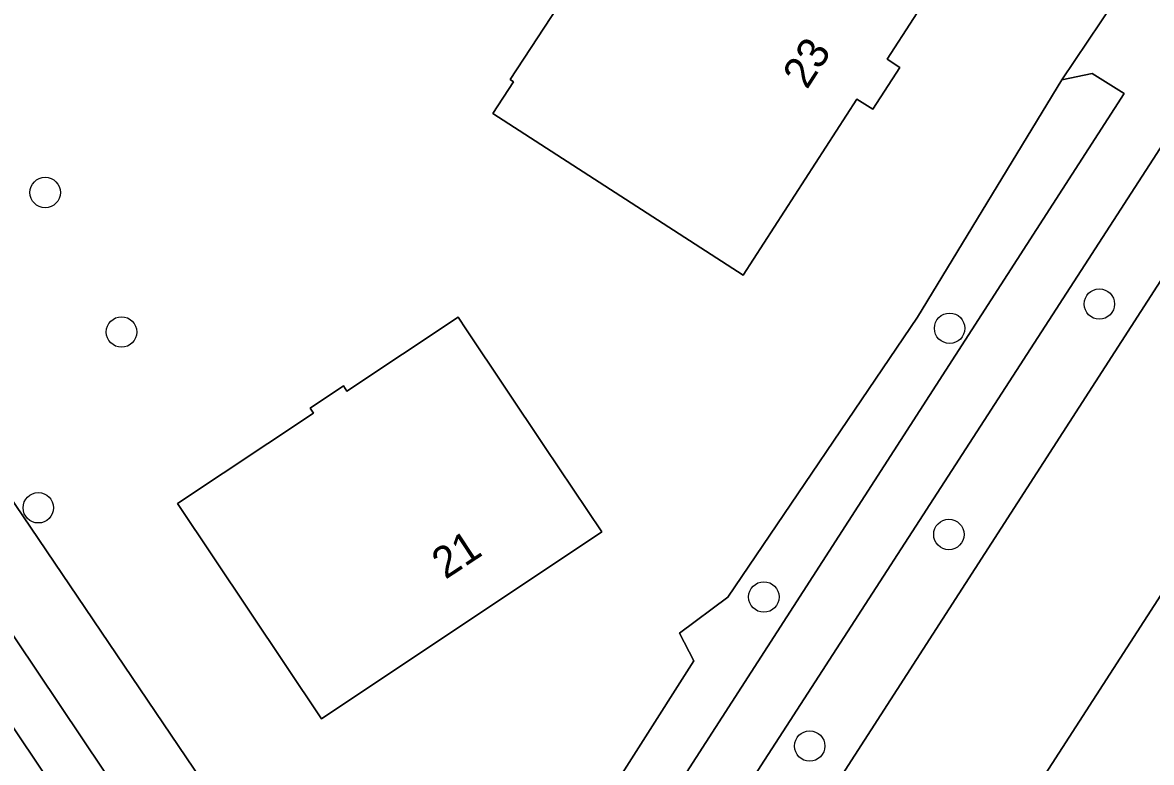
# Model space of a CAD drawing. Extents: x 158793 to 159888, y 384317 to 385256.
# Drawn here: x 158908.93 to 158945.21, y 384709.07 to 384732.84 of the extents above; entities that cross this region are included whole.
import ezdxf

# ---------------------------------------------------------------- set-up
doc = ezdxf.new("R2010")
doc.units = 0
for name, color, linetype in [('IMGEO_Berm_groen', 7, 'Continuous'), ('IMGEO_Boom', 7, 'Continuous'), ('IMGEO_Erf', 7, 'Continuous'), ('IMGEO_Groenvoorziening', 7, 'Continuous'), ('IMGEO_Pand', 7, 'Continuous'), ('IMGEO_Pand_nummerreeks', 7, 'Continuous'), ('IMGEO_Rijbaan_lokaal_open', 7, 'Continuous'), ('IMGEO_Voetpad_gesloten', 7, 'Continuous'), ('IMGEO_Voetpad_open', 7, 'Continuous')]:
    doc.layers.add(name, color=color, linetype=linetype)

msp = doc.modelspace()

# ---------------------------------------------------------------- linework, layer by layer
at = {"layer": 'IMGEO_Berm_groen'}
msp.add_lwpolyline([(158947.905, 384728.262), (158945.951, 384729.508), (158927.819, 384701.473), (158929.826, 384700.232)], close=True, dxfattribs=at)
msp.add_lwpolyline([(158951.852, 384724.265), (158938.197, 384703.116), (158942.084, 384700.551), (158942.526, 384699.967), (158952.229, 384685.559)], dxfattribs=at)
at = {"layer": 'IMGEO_Boom'}
for centre in [(158909.661, 384727.379), (158943.536, 384723.796), (158912.115, 384722.897), (158938.724, 384723.017), (158909.44, 384717.25), (158938.701, 384716.392), (158932.755, 384714.384), (158934.228, 384709.595)]:
    msp.add_circle(centre, 0.489, dxfattribs=at)
at = {"layer": 'IMGEO_Erf'}
msp.add_lwpolyline([(158951.086, 384827.221), (158939.626, 384810.234), (158935.537, 384804.144), (158926.293, 384790.814), (158922.895, 384785.874), (158911.021, 384768.255), (158908.919, 384765.124), (158902.963, 384756.125), (158899.474, 384750.866), (158892.722, 384740.964), (158921.437, 384698.523), (158922.798, 384700.654), (158924.704, 384703.639), (158925.321, 384704.179), (158930.5, 384712.328), (158930.039, 384713.226), (158931.6, 384714.377), (158937.688, 384723.377), (158942.331, 384730.999), (158945.25, 384735.359)], dxfattribs=at)
for points in [[(158940.106, 384736.899), (158936.719, 384731.662), (158937.125, 384731.4), (158936.259, 384730.054), (158935.738, 384730.375), (158932.09, 384724.725), (158924.046, 384729.914), (158924.708, 384730.939), (158924.607, 384731.005), (158930.08, 384739.364), (158928.014, 384740.701), (158929.552, 384743.078), (158927.869, 384744.166), (158929.188, 384746.205), (158937.122, 384741.073), (158936.099, 384739.491)], [(158927.55, 384716.477), (158918.541, 384710.469), (158913.915, 384717.384), (158918.286, 384720.287), (158918.176, 384720.454), (158919.246, 384721.165), (158919.357, 384720.998), (158922.93, 384723.372), (158923.203, 384722.964), (158925.71, 384719.223)]]:
    msp.add_lwpolyline(points, close=True, dxfattribs=at)
at = {"layer": 'IMGEO_Groenvoorziening'}
for points in [[(158899.474, 384750.866), (158898.193, 384752.685), (158897.889, 384752.896), (158891.624, 384743.655), (158892.649, 384742.981), (158890.664, 384739.928), (158891.203, 384739.123), (158893.901, 384735.12), (158920, 384696.198), (158920.219, 384696.537), (158921.771, 384695.549), (158924.407, 384699.588), (158922.798, 384700.654), (158921.437, 384698.523), (158892.722, 384740.964)], [(158892.825, 384733.792), (158888.897, 384736.52), (158917.762, 384692.731), (158919.023, 384694.684)], [(158944.331, 384730.562), (158943.308, 384731.203), (158942.331, 384730.999), (158937.688, 384723.377), (158931.6, 384714.377), (158930.039, 384713.226), (158930.5, 384712.328), (158925.321, 384704.179), (158924.704, 384703.639), (158926.304, 384702.596)]]:
    msp.add_lwpolyline(points, close=True, dxfattribs=at)
at = {"layer": 'IMGEO_Pand'}
for points in [[(158940.106, 384736.899), (158936.099, 384739.491), (158937.122, 384741.073), (158929.188, 384746.205), (158927.869, 384744.166), (158929.552, 384743.078), (158928.014, 384740.701), (158930.08, 384739.364), (158924.607, 384731.005), (158924.708, 384730.939), (158924.046, 384729.914), (158932.09, 384724.725), (158935.738, 384730.375), (158936.259, 384730.054), (158937.125, 384731.4), (158936.719, 384731.662)], [(158922.93, 384723.372), (158919.357, 384720.998), (158919.246, 384721.165), (158918.176, 384720.454), (158918.286, 384720.287), (158913.915, 384717.384), (158918.541, 384710.469), (158927.55, 384716.477), (158925.71, 384719.223), (158923.203, 384722.964)]]:
    msp.add_lwpolyline(points, close=True, dxfattribs=at)
at = {"layer": 'IMGEO_Rijbaan_lokaal_open'}
msp.add_lwpolyline([(158985.137, 384785.92), (158983.24, 384782.984), (158982.273, 384781.486), (158980.086, 384778.1), (158963.673, 384752.692), (158961.503, 384749.332), (158960.53, 384747.827), (158958.368, 384744.479), (158956.318, 384741.306), (158950.088, 384731.646), (158947.905, 384728.262), (158929.826, 384700.232), (158927.919, 384697.276), (158926.091, 384694.44), (158930.284, 384691.674), (158930.652, 384691.431), (158935.092, 384698.307), (158936.004, 384699.719), (158938.197, 384703.116), (158951.852, 384724.265), (158964.561, 384743.963), (158966.233, 384746.553), (158978.977, 384766.305)], dxfattribs=at)
at = {"layer": 'IMGEO_Voetpad_gesloten'}
msp.add_lwpolyline([(158893.901, 384735.12), (158891.203, 384739.123), (158890.664, 384739.928), (158889.689, 384738.429), (158890.519, 384737.206), (158892.46, 384734.337), (158892.825, 384733.792), (158919.023, 384694.684), (158920, 384696.198)], close=True, dxfattribs=at)
at = {"layer": 'IMGEO_Voetpad_open'}
for points in [[(158945.25, 384735.359), (158942.331, 384730.999), (158943.308, 384731.203), (158944.331, 384730.562), (158926.304, 384702.596), (158924.704, 384703.639), (158922.798, 384700.654), (158924.407, 384699.588), (158921.771, 384695.549), (158920.219, 384696.537), (158920, 384696.198), (158919.023, 384694.684), (158917.762, 384692.731), (158912.641, 384684.801), (158897.345, 384661.12)], [(158914.233, 384683.849), (158920.408, 384693.282), (158920.837, 384693.937), (158922.343, 384692.949), (158923.339, 384694.48), (158925.981, 384698.541), (158927.919, 384697.276), (158929.826, 384700.232), (158927.819, 384701.473), (158945.951, 384729.508)]]:
    msp.add_lwpolyline(points, dxfattribs=at)

# ---------------------------------------------------------------- texts
at = {"layer": 'IMGEO_Pand_nummerreeks'}
for s, rotation, p in [('23', 57.1525, (158934.139, 384730.664)), ('21', 33.5008, (158922.521, 384714.93))]:
    msp.add_text(s, height=1, rotation=rotation, dxfattribs=at).set_placement(p)

doc.saveas('drawing.dxf')
